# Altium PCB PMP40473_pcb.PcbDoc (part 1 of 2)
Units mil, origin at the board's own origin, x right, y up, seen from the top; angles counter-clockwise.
Board outline 3937.01 x 2598.43 mil, 2 copper layers (Top Layer, Bottom Layer), stack 62 mil thick; 79 components, 45 nets, 178 pads, 0 vias.
Unrouted connection lines stored in the file: 2.
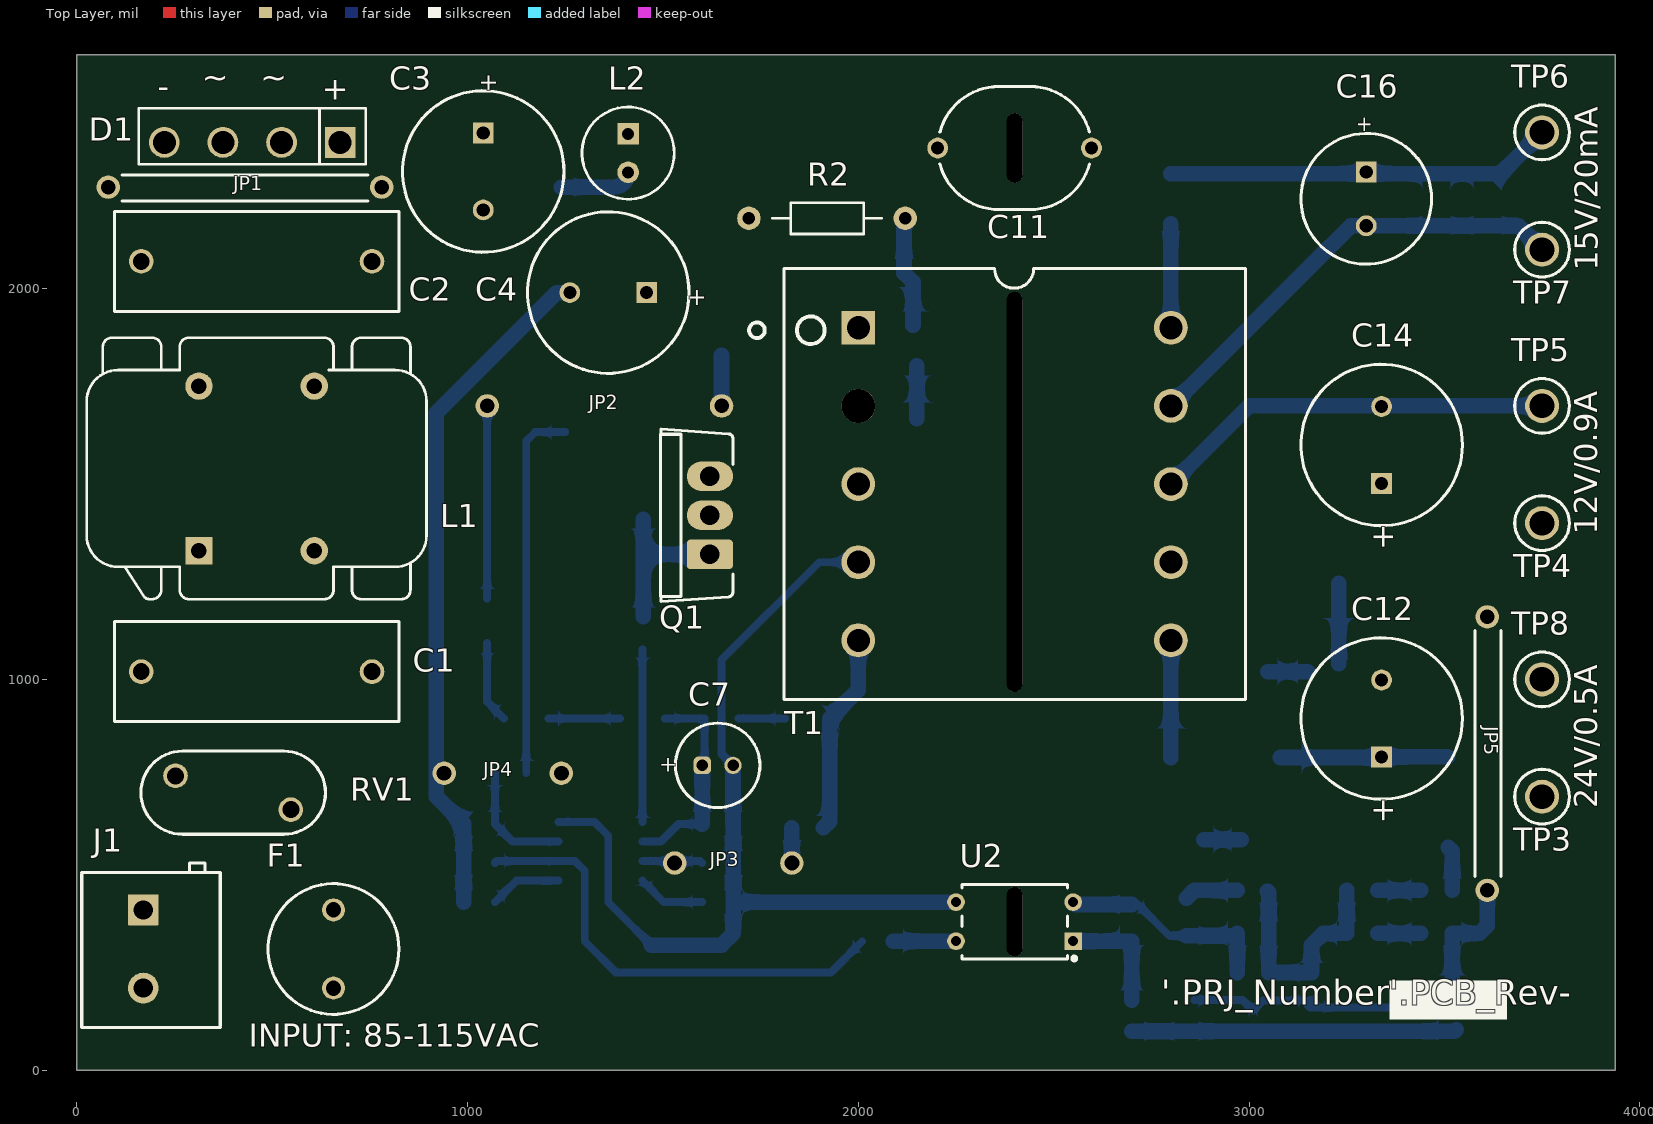
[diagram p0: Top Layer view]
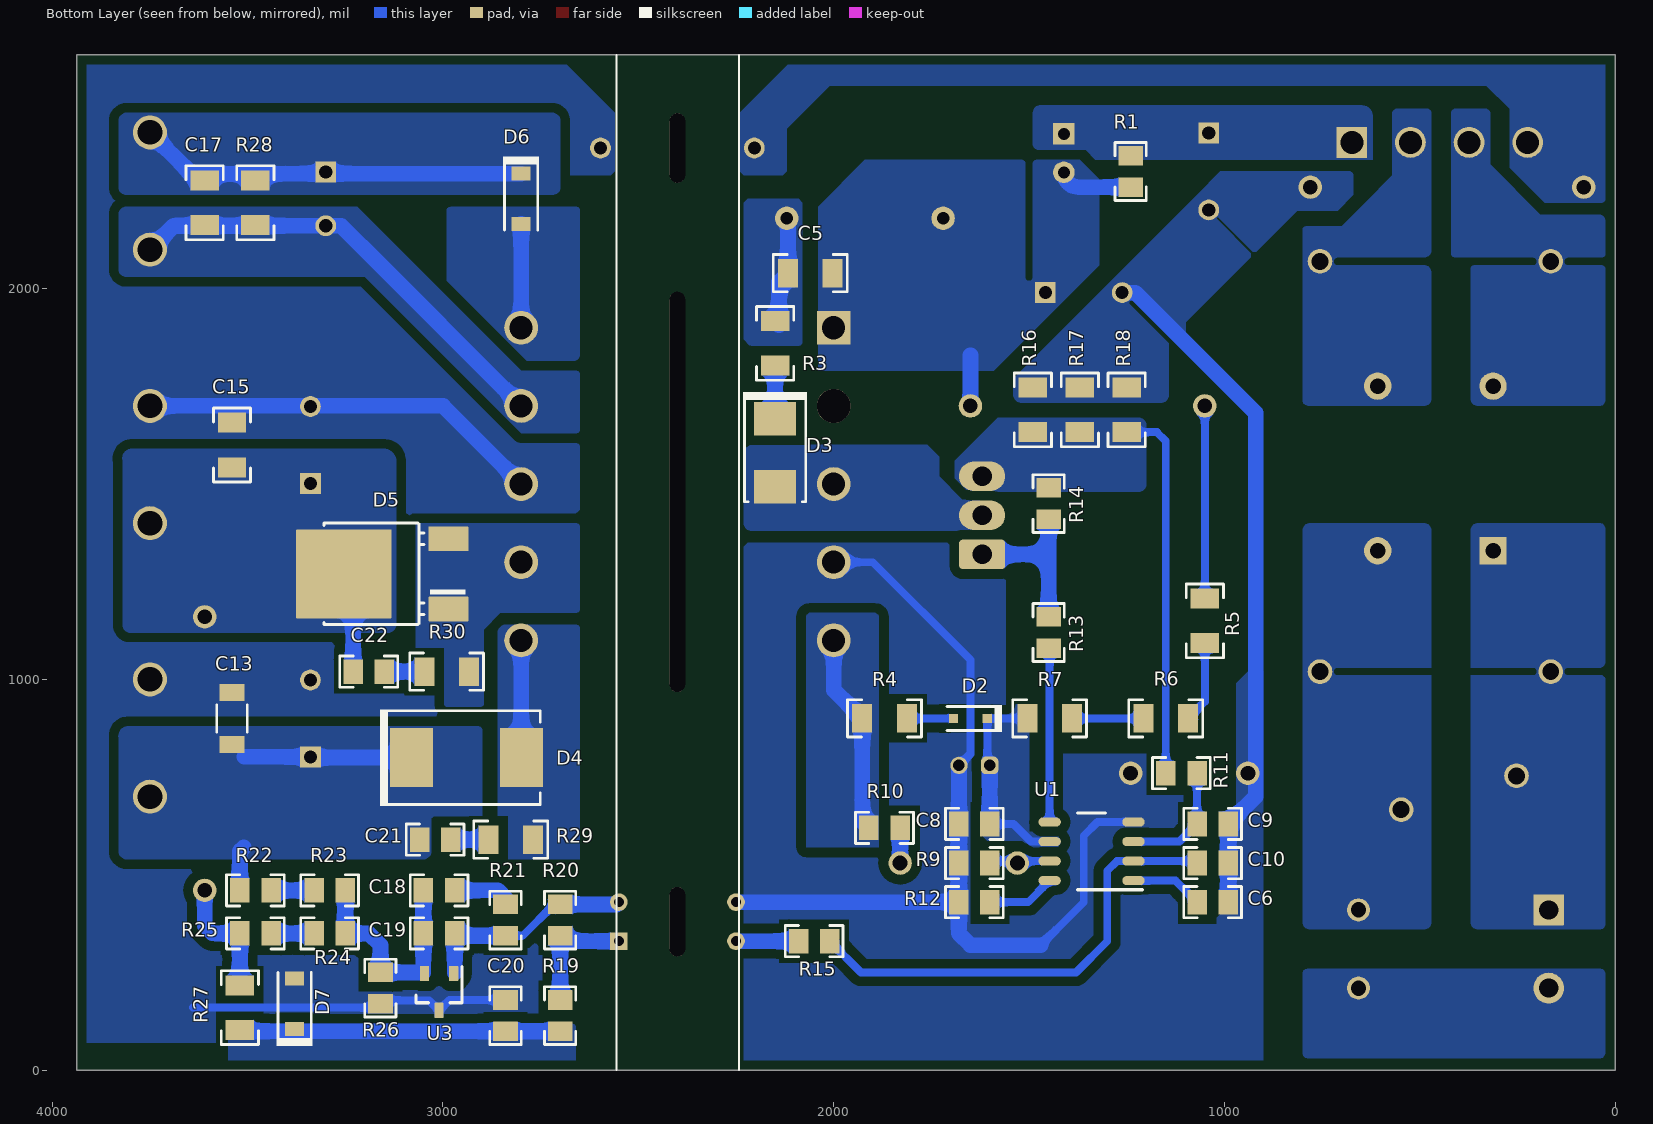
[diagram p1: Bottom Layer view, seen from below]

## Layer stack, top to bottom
Top Solder: solder mask 0.4, Solder Resist, Dk 3.5
Top Layer: signal copper 1.4
Dielectric1: core 59.2, FR-4, Dk 4.8
Bottom Layer: signal copper 1.4
Bottom Solder: solder mask 0.4, Solder Resist, Dk 3.5

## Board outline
0,0 3937.01,0 3937.01,2598.43 0,2598.43

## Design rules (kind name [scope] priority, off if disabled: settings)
AcuteAngle [All] p1: minimum=4.50000000000000E+0001 checktracksonly=FALSE
AssemblyTestPointUsage [All] p1: valid=2
BoardOutlineClearance BoardOutlineClearance_MountingHoles [OnCopper and InComponentClass('Mounting Holes')] p1: gap=40 ignorepadtopadclearanceinfootprint=FALSE
BoardOutlineClearance BoardOutlineClearance_Poly [OnCopper and IsPoly] p2: gap=25 ignorepadtopadclearanceinfootprint=FALSE
BoardOutlineClearance [OnCopper and Not InComponentClass('Logo') and not InComponentClass('FiducialMark') and not InRegion(1000,500,4000,800) and not InPoly] p3: gap=75 ignorepadtopadclearanceinfootprint=FALSE
Clearance Clearance_Keepouts [((IsTrack Or IsArc) And Not InPoly) And IsFree and IsKeepOut vs ((IsTrack Or IsArc) And Not InPoly) And IsFree and IsKeepOut] p1: gap=0 ignorepadtopadclearanceinfootprint=FALSE
Clearance Clearance_Poly [InPolygon] p2: gap=25 ignorepadtopadclearanceinfootprint=FALSE except(0: Arc-Hole Track-Hole SMDPad-Hole THPad-Hole Via-Hole Fill-Hole Poly-Hole Region-Hole Text-Hole)
Clearance Clearance_FiducialMark [IsKeepOut and InComponentClass('FiducialMark') vs IsPad and InComponentClass('FiducialMark')] p3: gap=0 ignorepadtopadclearanceinfootprint=FALSE
Clearance [All] p4: gap=7.87 ignorepadtopadclearanceinfootprint=FALSE except(0: Arc-Hole Track-Hole SMDPad-Hole THPad-Hole Via-Hole Fill-Hole Poly-Hole Region-Hole Text-Hole)
ComponentClearance ComponentClearance_MountingHoles_FiducialMarks [InComponentClass('Mounting Holes') vs InComponentClass('FiducialMark')] p1: gap=50 collisioncheckmode=3 verticalgap=10 showdistances=FALSE
ComponentClearance ComponentClearance_Shunt [InComponentClass('Header') vs InComponentClass('Shunt')] p2: gap=0 collisioncheckmode=3 verticalgap=0 showdistances=FALSE
ComponentClearance ComponentClearance_Logo [InComponentClass('Logo')] p3: gap=50 collisioncheckmode=3 verticalgap=10 showdistances=FALSE
ComponentClearance ComponentClearance_ScrewToNut [(HasFootprint('NY PMS 440 0025 PH')) vs (HasFootprint('Keystone_1902C'))] p4: gap=5 collisioncheckmode=3 verticalgap=10 showdistances=FALSE
ComponentClearance ComponentClearance_MountingHoles [InComponentClass('Mounting Holes')] p5: gap=250 collisioncheckmode=3 verticalgap=100000 showdistances=FALSE
ComponentClearance ComponentClearance_SmallPassives [HasFootprint('0201*') or HasFootprint('0402*') or HasFootprint('0508') or HasFootprint('0603*') or HasFootprint('0612') or HasFootprint('0805*') or HasFootprint('0815*') or HasFootprint('0830*') or HasFootprint('1206*') or HasFootprint('1210*') or HasFootprint('1808*') or HasFootprint('1812*') or HasFootprint('1825*') or HasFootprint('2010*') or HasFootprint('2220*') or HasFootprint('2225*') or HasFootprint('2512*') or HasFootprint('2728*') or HasFootprint('3518*') vs HasFootprint('0201*') or HasFootprint('0402*') or HasFootprint('0508') or HasFootprint('0603*') or HasFootprint('0612') or HasFootprint('0805*') or HasFootprint('0815*') or HasFootprint('0830*') or HasFootprint('1206*') or HasFootprint('1210*') or HasFootprint('1808*') or HasFootprint('1812*') or HasFootprint('1825*') or HasFootprint('2010*') or HasFootprint('2220*') or HasFootprint('2225*') or HasFootprint('2512*') or HasFootprint('2728*') or HasFootprint('3518*')] p6: gap=14.96 collisioncheckmode=3 verticalgap=10 showdistances=FALSE
ComponentClearance ComponentClearance_THtoSMT [IsThruComponent vs IsSMTComponent] p7: gap=40 collisioncheckmode=3 verticalgap=30 showdistances=FALSE
ComponentClearance ComponentClearance_THtoTH [IsThruComponent vs IsThruComponent] p8: gap=30 collisioncheckmode=3 verticalgap=30 showdistances=FALSE
ComponentClearance [All] p9: gap=30 collisioncheckmode=3 verticalgap=10 showdistances=FALSE
DiffPairsRouting [All] p1: maxlimit=100 minlimit=10 mostfreqgap=10 toplayer_minwidth=15 toplayer_maxwidth=15 toplayer_prefwidth=15 bottomlayer_minwidth=15 bottomlayer_maxwidth=15 bottomlayer_prefwidth=15 maxuncoupledlength=1000
FabricationTestPointUsage TestPointUsage [All] p1: valid=2 allowmultiple=FALSE
FabricationTestpoint Testpoint [All] p1: side=3 testpointundercomponent=TRUE minsize=40 maxsize=100 preferedsize=60 minholesize=0 maxholesize=40 preferedholesize=32 testpointgrid=1 allowsidetop=TRUE allowsidebottom=TRUE usegrid=TRUE gridtolerance=0.01
FanoutControl Fanout_LCC [IsLCC] p1: bgadir=Out bgaviamode=Centered fanoutstyle=Auto fanoutdirection=Alternating viagrid=1 // Fanout_LCC (Default Rule)
FanoutControl Fanout_BGA [IsBGA] p2: bgadir=Out bgaviamode=Centered fanoutstyle=Auto fanoutdirection=Alternating viagrid=1 // Fanout_BGA (Default Rule)
FanoutControl Fanout_Default [All] p4: bgadir=Out bgaviamode=Centered fanoutstyle=Auto fanoutdirection=Alternating viagrid=1 // Fanout_Default (Default Rule)
FanoutControl Fanout_Small [(CompPinCount < 5)] p5: bgadir=Out bgaviamode=Centered fanoutstyle=Auto fanoutdirection=OutThenIn viagrid=1 // Fanout_Small (Default Rule)
HoleSize [All] p1: absolutevalues=TRUE maxlimit=251 minlimit=7.87 maxpercent=80.000 minpercent=20.000
MinimumAnnularRing MinimumAnnularRing_ThermalPadVias [IsVia and InAnyComponent] p1: minimumring=5.91
MinimumAnnularRing [All] p2: minimumring=8
MinimumSolderMaskSliver MinimumSolderMaskSliver_Logo [InComponentClass('Logo') vs InComponentClass('Logo')] p1: minsoldermaskwidth=0.7
MinimumSolderMaskSliver [All] p2: minsoldermaskwidth=3.94
PlaneConnect [All] p1: planeconnectstyle=Relief reliefexpansion=10 reliefentries=4 reliefconductorwidth=10 reliefairgap=10
PolygonConnect [All] p1: connectstyle=Direct reliefconductorwidth=10 reliefentries=4 polygonreliefangle="90 Angle" airgapwidth=10
RoutingVias ThermalPadVias [IsVia and InAnyComponent] p1: holewidth=7.87 width=19.68 viastyle="Through Hole" minholewidth=7.87 minwidth=19.68 maxholewidth=12.99 maxwidth=23.62
RoutingVias [All] p2: holewidth=16 width=34 viastyle="Through Hole" minholewidth=7.87 minwidth=26 maxholewidth=40 maxwidth=65
SilkToBoardRegionClearance [Not ((IsComment or IsDesignator) And (Hide <> 'False')) and not InRegion(1000,500,4000,800)] p1:
SilkToSilkClearance SilkToSilkClearance_Pb-FreeLogo [(HasFootprint('Pb-Free_Overlay_Medium') OR HasFootprint('Pb-Free_Overlay_Small')) vs (HasFootprint('Pb-Free_Overlay_Medium') OR HasFootprint('Pb-Free_Overlay_Small'))] p1: silktosilkclearance=0
SilkToSilkClearance [All] p2: silktosilkclearance=4
SilkToSolderMaskClearance SilkToComponentPadClearance [(IsPad or IsFill or IsRegion) and InAnycomponent] p1: minsilkscreentomaskgap=5 clearancetoexposedcopper=TRUE
SilkToSolderMaskClearance "Silk to Solder Mask Opening" [All] p2: minsilkscreentomaskgap=4 clearancetoexposedcopper=FALSE
SolderMaskExpansion [All] p1: expansion=1.97
Width [All] p1: maxlimit=100 minlimit=20 preferedwidth=40 checkconnectedcopper=TRUE
15 further rules are at their usual default settings.

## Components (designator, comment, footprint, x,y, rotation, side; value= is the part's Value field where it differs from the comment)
C1 "890324025017" WCAP-FTX2_1800x600x1200 460,1020 r180 top value=0.1uF
C2 "890324025017" WCAP-FTX2_1800x600x1200 460,2070 r180 top value=0.1uF
C3 "EKXG201ELL330MJ20S" KL_1000x2000 1040,2300 r270 top value=33uF
C4 "EKXG201ELL330MJ20S" KL_1000x2000 1360,1990 r180 top value=33uF
C5 "GRM31BR72J222KW01L" 1206 2060,2040 r0 bottom value=2200pF
C6 "CC0805KRX7R9BB103" 0805_HV 1030,430 r0 bottom value=0.01uF
C7 "35YXH33MEFC5X11" Rubycon_500x1100 1640,780 r0 top value=33uF
C8 "C0805C104K5RACTU" 0805_HV 1640,630 r0 bottom value=0.1uF
C9 "GRM216R71E102KA01D" 0805_HV 1030,630 r180 bottom value=1000pF
C10 "GRM216R71E681KA01D" 0805_HV 1030,530 r180 bottom value=680pF
C11 "DE1E3KX222MA5BA01" CAPRD1000W60D1000H1400 2400,2360 r0 top value=2200pF
C12 "EKZE350ELL471MJ20S" Chemi-Con_1000x2000 3339.37,900 r90 top value=470uF
C13 "C3216X7R1H105K160AB" 1206_180 3540,900 r90 bottom value=1uF
C14 "EKMG250ELL102MJ20S" Chemi-Con_1000x2000 3339.37,1600 r90 top value=1000uF
C15 "C1206C105K3RACTU" 1206 3540,1600 r90 bottom value=1uF
C16 "EKMG250ELL221MHB5D" Chemi-Con_800x1150 3300,2230 r270 top value=220uF
C17 "C1206C105K3RACTU" 1206 3610,2220 r270 bottom value=1uF
C18 "C2012X7R1H224K125AA" 0805_HV 3010,460 r180 bottom value=0.22uF
C19 "08055C471KAT2A" 0805_HV 3010,350 r180 bottom value=470pF
C20 "GRM21BR71E104KA01L" 0805_HV 2840,139.5 r90 bottom value=0.1uF
C21 "GRM21BR71E104KA01L" 0805_HV 3020,590 r0 bottom value=0.1uF
C22 "GRM21BR71E104KA01L" 0805_HV 3190,1020 r0 bottom value=0.1uF
D1 "KBP06G" KBP 448.82,2374.33 r180 top value=600V
D2 "BAS20HT1G" SOD-323 1650,900 r0 bottom value=200V
D3 "RS1MB-13-F" SMB 2150,1580 r270 bottom value=1000V
D4 "B3100-13-F" SMC 2940,800 r180 bottom value=100V
D5 "MBRD360T4G" DPAK 3120,1270 r0 bottom value=60V
D6 "SBR0560S1-7" SOD-123 2800,2230 r270 bottom value=60V
D7 "MMSZ5242B-7-F" SOD-123 3380,170 r90 bottom value=12V
F1 "37205000001" FUSE_372 656.85,310 r90 top
J1 "ED120/2DS" On-Shore_ED120_2DS 170,310 r270 top
JP1 "923345-20-C" CONN_923345-07-C 430,2260 r0 top
JP2 "923345-20-C" CONN_923345-06-C 1350,1700 r0 top
JP3 "923345-20-C" 923345-03-C 1680,530 r0 top
JP4 "923345-20-C" 923345-03-C 1090,760 r180 top
JP5 "923345-20-C" CONN_923345-07-C 3610,810 r90 top
L1 "744823210" WE-CMB_M 460,1540 r90 top value=10mH
L2 "Inductor Iron" WE-TI_5075 1410.95,2347.09 r270 top value=220uH
Q1 "SPP06N80C3" TO-220AB 1620,1420 r90 top value=800V
R1 "Res2" 0805_HV 1240,2300 r270 bottom value=10.0k
R2 "CMF50150K00FHEB" CMF50 1920,2180 r180 top value=150k
R3 "CRCW120630R0JNEA" 1206 2150,1860 r90 bottom value=30
R4 "RC1206JR-070RL" 1206 1870,900 r0 bottom value=0
R5 "CRCW1206330KJNEA" 1206 1050,1150 r90 bottom value=330k
R6 "CRCW1206330KJNEA" 1206 1150,900 r180 bottom value=330k
R7 "CRCW1206330KJNEA" 1206 1447.28,900 r180 bottom value=330k
R9 "CRCW0805100KJNEA" 0805_HV 1640,530 r180 bottom value=100k
R10 "CRCW0805510KJNEA" 0805_HV 1870,620 r0 bottom value=510k
R11 "CRCW08051K50JNEA" 0805_HV 1110,760 r0 bottom value=1.5k
R12 "CRCW080510K0JNEA" 0805_HV 1640,430 r180 bottom value=10k
R13 "CRCW080510R0JNEA" 0805_HV 1450,1120 r270 bottom value=10
R14 "CRCW080547K0JNEA" 0805_HV 1450,1450 r270 bottom value=47k
R15 "CRCW08050000Z0EA" 0805_HV 2050,330 r180 bottom value=0
R16 "CRCW12061R50JNEA" 1206 1490,1690 r270 bottom value=1.5
R17 "CRCW12061R50JNEA" 1206 1370,1690 r270 bottom value=1.5
R18 "CRCW12061R50JNEA" 1206 1250,1690 r270 bottom value=1.5
R19 "CRCW08056K80JNEA" 0805_HV 2700,139.5 r90 bottom value=6.8k
R20 "CRCW08051K00JNEA" 0805_HV 2700,384 r90 bottom value=1.0k
R21 "CRCW080510K0JNEA" 0805_HV 2840,384 r270 bottom value=10k
R22 "CRCW08052K70JNEA" 0805_HV 3480,460 r0 bottom value=2.7k
R23 "CRCW080533K0JNEA" 0805_HV 3290,460 r0 bottom value=33k
R24 "CRCW080515K0FKEA" 0805_HV 3290,350 r0 bottom value=15.0k
R25 "CRCW08052K70JNEA" 0805_HV 3480,350 r0 bottom value=2.7k
R26 "CRCW08052K20JNEA" 0805_HV 3160,210 r90 bottom value=2.2k
R27 "CRCW120622R0JNEA" 1206 3520,160 r270 bottom value=22
R28 "CRCW120610K0JNEA" 1206 3480,2220 r90 bottom value=10k
R29 "CRCW120610K0JNEA" 1206 2826.64,590 r180 bottom value=10k
R30 "CRCW120610K0JNEA" 1206 2990.55,1020 r180 bottom value=10k
RV1 "S10K275E2" VAR_S10K275E2 400,710 r0 top value=275V
T1 "XFMR_RLTI-1072" EE25-13-7_2607 2400,1500 r0 top value=RLTI-1072
TP3 "5010" Keystone5010 3750,700 r90 top
TP4 "5010" Keystone5010 3750,1400 r90 top
TP5 "5011" Keystone5011 3750,1700 r90 top
TP6 "5010" Keystone5010 3750,2400 r90 top
TP7 "5011" Keystone5011 3750,2100 r90 top
TP8 "5011" Keystone5011 3750,1000 r90 top
U1 "UCC28600D" D0008A_N 1340,560 r0 bottom
U2 "FOD817A" DIP-4 2400,380 r180 top
U3 "TL431AIDBZT" DBZ0003A_N 3010,200 r270 bottom

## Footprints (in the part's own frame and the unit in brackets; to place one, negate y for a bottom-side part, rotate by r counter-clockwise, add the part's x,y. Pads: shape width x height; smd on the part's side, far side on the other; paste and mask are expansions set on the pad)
0805_HV [mil] "0805 with 30mil clearance between pads"
  rect 50x63 smd: 1(-40,0) 2(40,0)
  silkscreen extent -74,-40 74,40, body extent -43,-29 43,29, height 57
1206 [mm] "1206 from SM-752 data"
  rect 1.3x1.85 smd: 1(-1.45,0) 2(1.45,0)
  silkscreen extent -2.4,-1.21 2.4,1.21, body extent -1.7,-0.9 1.7,0.9, height 1.35
1206_180 [mm] "1206_180"
  rect 1.1x1.6 smd: 1(-1.7,0) 2(1.7,0)
  silkscreen extent -0.9,-1 0.9,1, body extent -1.75,-0.95 1.75,0.95, height 1.8
923345-03-C [mil] "Wire Jumper"
  round 60 hole 38: 1(-150,0) 2(150,0)
  body extent -163,-40 163,37, height 100
CAPRD1000W60D1000H1400 [mm] "Disk, Radial Capacitor"
  round 1.35 hole 0.85: 1(-5,0) 2(5,0)
  silkscreen extent -4.86,-4 4.86,4, body extent -5.67,-4 5.7,4, height 13.99
Chemi-Con_800x1150 [mm] "TH, 2-Leads, Dia 8mm"
  rect 1.35x1.35 hole 0.85: 1(-1.75,0)
  round 1.35 hole 0.85: 2(1.75,0)
  silkscreen extent -4.25,-4.25 4.25,4.25, body extent -4.22,-4.24 4.24,4.24, height 13.01
Chemi-Con_1000x2000 [mm] "TH, 2-Leads, Body 10x20mm, Pin Spacing 5mm"
  rect 1.35x1.35 hole 0.85: 1(-2.5,0)
  round 1.35 hole 0.85: 2(2.5,0)
  silkscreen extent -5.25,-5.25 5.25,5.25, body extent -5.25,-5.25 5.25,5.25, height 21.5
CMF50 [mil] "VIshay Metal Film Resistors 1/4W"
  round 60 hole 32: 1(-200,0) 2(200,0)
  silkscreen extent -140,-40 140,40, body extent -214,-40 214,40, height 80
CONN_923345-06-C [mil] "3M, Wire jumper, 600 mil lenght, Blue"
  round 60 hole 37: 1(-300,0) 2(300,0)
  body extent -313,-35 314,35, height 70
CONN_923345-07-C [mil] "3M, Wire jumper, 700 mil lenght, Violet"
  round 60 hole 37: 1(-350,0) 2(350,0)
  silkscreen extent -315,-35 315,31, body extent -363,-33 363,33, height 74
D0008A_N [mm] "SOIC, 8-Leads, Body 4.9x3.9mm, Pitch 1.27mm, IPC Medium Density"
  oval 1.45x0.6 smd: 1(-2.725,1.905) 2(-2.725,0.635) 3(-2.725,-0.635) 4(-2.725,-1.905) 5(2.725,-1.905) 6(2.725,-0.635) 7(2.725,0.635) 8(2.725,1.905)
  silkscreen extent -3.3,-2.5 0.9,2.5, body extent -3,-2.45 3,2.45, height 1.63
DBZ0003A_N [mm] "SOT23, 3-Leads, Body 2.9x1.3mm, Pitch 0.95mm, Lead Span 2.4mm, IPC Medium Density"
  rrect17% 1x0.6 smd: 1(-1.2,0.95) 2(-1.2,-0.95) 3(1.2,0)
  silkscreen extent -1.65,-1.5 0.7,1.5, body extent -1.26,-1.46 1.26,1.46, height 0.98
DIP-4 [mm] "DIP, 4-Leads, Body 6.86x4.83mm, Pitch 2.54mm"
  rect 1.15x1.15 hole 0.65: 1(-3.81,1.27)
  round 1.15 hole 0.65: 2(-3.81,-1.27) 3(3.81,-1.27) 4(3.81,1.27)
  silkscreen extent -4,-2.41 3.43,2.52, body extent -4.02,-2.41 4.02,2.41, height 5.59
DPAK [mm] "D-PAK, 3-Pads, Body 6.22x6.73mm (max), TO-252AA using nominal STEP model"
  rrect6% 2.6x1.6 smd: 1(-3.4,2.28) 3(-3.4,-2.28)
  rrect2% 6.2x5.8 smd paste-2.9: 4(3.4,0)
  silkscreen extent -4.5,-3.3 4.7,3.28, body extent -3.86,-3.29 5.84,3.29, height 2.48
EE25-13-7_2607 [mm] "THT, Body 29.21x27.94mm, 10Pins, Pitch 5.08mm"
  rect 2.2x2.2 hole 1.5: 1(-10.16,10.16)
  round 2.2 hole 2.2: 2(-10.16,5.08)
  round 2.2 hole 1.5: 3(-10.16,0) 4(-10.16,-5.08) 5(-10.16,-10.16) 6(10.16,-10.16) 7(10.16,-5.08) 8(10.16,0) 9(10.16,5.08) 10(10.16,10.16)
  silkscreen extent -17.26,-14 15,14, body extent -14,-13.75 14,13.75, height 19.91
FUSE_372 [mm] "LITTELFUSE"
  round 1.5 hole 1: 1(-2.54,0) 2(2.54,0)
  silkscreen extent -4.25,-4.25 4.25,4.25, body extent -4.25,-4.25 4.25,4.25, height 8
KBP [mm] "Diodes Inc Bridge Rectifier"
  rect 2x2 hole 1.5: 1(-5.715,0)
  round 2 hole 1.5: 2(-1.905,0) 3(1.905,0) 4(5.715,0)
  silkscreen extent -7.37,-2.23 7.38,1.42, body extent -7.37,-2.23 7.38,1.42, height 12.91
Keystone5010 [mil] "Keystone Multipurpose loops"
  round 87 hole 63: 1(0,0)
  silkscreen extent -70,-70 70,70, body extent -63,-63 63,62, height 319
Keystone5011 [mil] "Keystone Multipurpose loops"
  round 87 hole 63: 1(0,0)
  silkscreen extent -70,-70 70,70, body extent -63,-63 63,62, height 319
KL_1000x2000 [mm] "TH, 2-Leads, Dia 10mm, Pin Spacing 5mm"
  rect 1.35x1.35 hole 0.85: 1(-2.5,0)
  round 1.35 hole 0.85: 2(2.5,0)
  silkscreen extent -5.25,-5.25 5.25,5.25, body extent -5.25,-5.25 5.26,5.25, height 21.51
On-Shore_ED120_2DS [mm] "ONSHORE"
  rrect5% 2x2 hole 1.25: 1(-2.54,0)
  round 2 hole 1.25: 2(2.54,0)
  silkscreen extent -5.6,-4 5.12,5, body extent -5.78,-4 5.08,5, height 13
Rubycon_500x1100 [mm] "TH, 2-Leads, Dia 5mm,  Lead Spacing 2mm"
  rrect50% 1.125x1.125 hole 0.75: 1(-1,0)
  round 1.125 hole 0.75: 2(1,0)
  silkscreen extent -2.75,-2.75 2.75,2.75, body extent -2.73,-2.75 2.75,2.75, height 12.51
SMB [mil] "Molded Diode, 2-Leads, Body 5.4x3.6mm, IPC Medium Density, based on OnSemi component dimensions"
  rect 85x107.99 smd: 1(-87.01,0) 2(87.01,0)
  silkscreen extent -155,-82 125,82, body extent -106,-71 106,71, height 91
SMC [mil] "Molded Diode, 2-Leads, Body 6.9x5.8mm, IPC Medium Density, based on OnSemi component dimensions and land patterns"
  rect 110x150 smd: 1(-140.49,0) 2(140.49,0)
  silkscreen extent -221,-123 189,124, body extent -156,-116 156,116, height 91
SOD-123 [mm] "On Semi recommended land pattern"
  rect 0.915x1.22 smd: 1(-1.637,0) 2(1.637,0)
  silkscreen extent -2.74,-1.17 2.03,1.17, body extent -1.93,-0.9 1.93,0.9, height 1.35
SOD-323 [mm] "NXP recommended land pattern"
  rect 0.6x0.6 smd paste-0.05: 1(-1.1,0) 2(1.1,0)
  silkscreen extent -2.06,-0.86 1.53,0.86, body extent -1.3,-0.67 1.3,0.68, height 1.1
TO-220AB [mil] "Copied from Altium's version of TO3B"
  rrect25% 76x118.11 hole 50: 1(-100,0)
  oval 76x118.11 hole 50: 2(0,0) 3(100,0)
  silkscreen extent -221,-59 221,126, body extent -221,-59 221,126, height 765
VAR_S10K275E2 [mm] "EPCOS"
  round 1.6 hole 1.1: 1(-3.75,1.1) 2(3.75,-1.1)
  silkscreen extent -6,-2.7 6,2.7, body extent -5.98,-2.7 5.98,2.7, height 14.99
WCAP-FTX2_1800x600x1200 [mm] "TH, 2-Leads, Body 18x6mm, Lead Spacing 15mm"
  round 1.6 hole 1.1: 1(-7.5,0) 2(7.5,0)
  silkscreen extent -9.25,-3.25 9.25,3.25, body extent -9.25,-3.25 9.25,3.25, height 12.5
WE-CMB_M [mil] "Wurth"
  rect 70x70 hole 40: 1(-210.63,147.64)
  round 70 hole 40: 2(-210.63,-147.64) 3(210.63,-147.64) 4(210.63,147.64)
  silkscreen extent -335,-435 335,435, body extent -335,-394 335,394, height 1044
WE-TI_5075 [mm] "Wurth WE-TI 5075"
  rect 1.4x1.4 hole 0.787: 1(-1.25,0)
  round 1.4 hole 0.787: 2(1.25,0)
  silkscreen extent -3,-3 3,3, body extent -3,-3 3,3, height 8.5

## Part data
C1 C2: "CAP, Film, 0.1 µF, X2 275 VAC, +/- 10%, TH", Cap_Case=18x6x12mm, Manufacturer="Wurth Elektronik", Supplier Part Number 1=732-5898-ND, Tolerance_%=10, ValueDisplayed=0.1µF
C3 C4: library part EKXG401EC3330ML20S, "CAP, AL, 33 µF, 400 V, +/- 20%, TH", Cap_Case=10x20mm, Manufacturer=Chemi-Con, Tolerance_%=20, Value2=200V, ValueDisplayed=33µF
C5: "CAP, CERM, 2200 pF, 630 V,+/- 10%, X7R, 1206", Cap_Case=1206, Manufacturer=MuRata, Supplier Part Number 1=490-3508-1-ND, TempCo=X7R, Tolerance_%=10, Value2=630V, ValueDisplayed=2200pF
C6: "CAP, CERM, 0.01 µF, 50 V,+/- 10%, X7R, 0805", Cap_Case=0805, Manufacturer="Yageo America", Supplier Part Number 1=311-1136-1-ND, TempCo=X7R, Tolerance_%=10, Value2=50V, ValueDisplayed=0.01µF
C7: "CAP, AL, 33 µF, 35 V, +/- 20%, TH", Cap_Case=5x11mm, Manufacturer=Rubycon, Supplier Part Number 1=35YXH33MEFC5X11-ND, Tolerance_%=20, Value2=35V, ValueDisplayed=33µF
C8: "CAP, CERM, 0.1 µF, 50 V,+/- 10%, X7R, 0805", Cap_Case=0805, Manufacturer=Kemet, Supplier Part Number 1=399-1170-1-ND, TempCo=X7R, Tolerance_%=10, Value1="0.064 ohm", Value2=50V, ValueDisplayed=0.1µF
C9: "CAP, CERM, 1000 pF, 25 V,+/- 10%, X7R, 0805", Cap_Case=0805, Manufacturer=MuRata, Supplier Part Number 1=GRM216R71E102KA01D-ND, TempCo=X7R, Tolerance_%=10, Value2=25V, ValueDisplayed=1000pF
C10: "CAP, CERM, 680 pF, 25 V,+/- 10%, X7R, 0805", Cap_Case=0805, Manufacturer=MuRata, Supplier Part Number 1=GRM216R71E681KA01D-ND, TempCo=X7R, Tolerance_%=10, Value2=25V, ValueDisplayed=680pF
C11: "CAP, CERM, 2200 pF, 250 V, +/- 20%, E, Disc 10x8mm", Cap_Case=CAPRD1000W60D1000H1400, Manufacturer=MuRata, Supplier Part Number 1=490-7048-ND, TempCo=E, Tolerance_%=20, Value1=Unknown, Value2=250V, ValueDisplayed=2200pF
C12: "CAP, AL, 470 µF, 35 V, +/- 20%, TH", Cap_Case=10x20, Manufacturer=Chemi-Con, Supplier Part Number 1=565-1694-ND, Tolerance_%=20, Value2=35V, ValueDisplayed=470µF
C13: "CAP, CERM, 1 µF, 50 V,+/- 10%, X7R, 1206", Cap_Case=1206, Manufacturer=TDK, Supplier Part Number 1=445-1423-1-ND, TempCo=X7R, Tolerance_%=10, Value1="0.009289 ohm", Value2=50V, ValueDisplayed=1µF
C14: "CAP, AL, 1000 µF, 25 V, +/- 20%, TH", Cap_Case=10x20mm, Manufacturer=Chemi-Con, Supplier Part Number 1=565-1311-ND, Tolerance_%=20, Value2=25V, ValueDisplayed=1000µF
C15 C17: "CAP, CERM, 1 µF, 25 V,+/- 10%, X7R, 1206", Cap_Case=1206, Manufacturer=Kemet, Supplier Part Number 1=399-1255-1-ND, TempCo=X7R, Tolerance_%=10, Value1="0.011 ohm", Value2=25V, ValueDisplayed=1µF
C16: "CAP, AL, 220 µF, 25 V, +/- 20%, TH", Cap_Case=8x11.5mm, Manufacturer=Chemi-Con, Supplier Part Number 1=565-1308-ND, Tolerance_%=20, Value2=25V, ValueDisplayed=220µF
C18: "CAP, CERM, 0.22 µF, 50 V,+/- 10%, X7R, 0805", Cap_Case=0805, Manufacturer=TDK, Supplier Part Number 1=445-1350-1-ND, TempCo=X7R, Tolerance_%=10, Value1="0.016949 ohm", Value2=50V, ValueDisplayed=0.22µF
C19: "CAP, CERM, 470 pF, 50 V,+/- 10%, X7R, 0805", Cap_Case=0805, Manufacturer=AVX, Supplier Part Number 1=478-1367-1-ND, TempCo=X7R, Tolerance_%=10, Value1="0.454 ohm", Value2=50V, ValueDisplayed=470pF
C20 C21 C22: "CAP, CERM, 0.1 µF, 25 V,+/- 10%, X7R, 0805", Cap_Case=0805, Manufacturer=MuRata, Supplier Part Number 1=490-1673-1-ND, TempCo=X7R, Tolerance_%=10, Value2=25V, ValueDisplayed=0.1µF
D1: "Diode, Switching-Bridge, 600 V, 1.5 A, TH", Manufacturer="Diodes Inc.", Supplier Part Number 1=KBP06G-ND, Value1=1.5A, Value2=1.1V
D2: "Diode, Switching, 200 V, 0.2 A, AEC-Q101, SOD-323", Manufacturer="ON Semiconductor", Supplier Part Number 1=BAS20HT1GOSCT-ND, Value1=0.2A, Value2=1.25V
D3: "Diode, P-N, 1000 V, 1 A, SMB", Manufacturer="Diodes Inc.", Supplier Part Number 1=RS1MB-FDICT-ND, Value1=1A, Value2=1.3V
D4: "Diode, Schottky, 100 V, 3 A, SMC", Manufacturer="Diodes Inc.", Supplier Part Number 1=B3100-FDICT-ND, Value1=3A, Value2=0.79V
D5: "Diode, Schottky, 60 V, 3 A, DPAK", Manufacturer="ON Semiconductor", Supplier Part Number 1=MBRD360T4GOSCT-ND, Value1=3A, Value2=0.6V
D6: "Diode, Schottky, 60 V, 0.5 A, SOD-123", Manufacturer="Diodes Inc.", Supplier Part Number 1=SBR0560S1DICT-ND, Value1=0.5A, Value2=0.5V
D7: "Diode, Zener, 12 V, 500 mW, SOD-123", Manufacturer="Diodes Inc.", Power_W=0.5, Supplier Part Number 1=MMSZ5242B-FDICT-ND, Value1=0.5W
F1: "Fuse, 0.5 A, 250VAC/VDC, TH", Irating_A=0.5, Manufacturer=Littelfuse, Supplier Part Number 1=WK4241CT-ND
J1: library part CMP-0074910-1, "Terminal Block, 5.08 mm, 2x1, Brass, TH", Color=Blue, Current_A=15A, Manufacturer="On-Shore Technology", Supplier Part Number 1=ED1609-ND, Voltage_V=300V
JP1 JP5: library part CMP-0074936-1, "Jumper Wire, 700mil spacing, Violet, pkg of 150, TH", Manufacturer=3M, PartNumber=923345-07-C, Supplier Part Number 1=923345-07-ND
JP2: library part CMP-0074937-1, "Jumper Wire, 600mil spacing, Blue, pkg of 150, TH", Manufacturer=3M, PartNumber=923345-06-C, Supplier Part Number 1=923345-06-ND
JP3 JP4: library part CMP-0055440-1, "Jumper Wire, 300mil spacing, Orange, pkg of 200", Manufacturer=3M, PartNumber=923345-03-C, Supplier Part Number 1=923345-03-ND
L1: "Coupled inductor, 10 mH, 2 A, 0.125 ohm, TH", Manufacturer="Wurth Elektronik", Supplier Part Number 1=732-1447-ND, ValueDisplayed=10mH
L2: library part 7447462221, "Inductor, Unshielded Drum Core, Ferrite, 220 µH, 0.5 A, 0.96 ohm, TH", Manufacturer="Wurth Elektronik", Supplier Part Number 1=732-2574-ND, Value1="0.96 ohm", Value2=0.5A, ValueDisplayed=220µH
Q1: "MOSFET, N-CH, 800 V, 6 A, TO-220AB", Alternate Manufacturer=None, Manufacturer="Infineon Technologies", Supplier Part Number 1=SPP06N80C3IN-ND, Value1="0.9 ohm", Value2="41 nC"
R1: library part CRCW080510K0FKEA, "RES, 10.0 k, 1%, 0.125 W, 0805", Manufacturer=Vishay-Dale, Power_W=0.125, Supplier Part Number 1=541-10.0KCCT-ND, TempCo="100 ppm/C", Tolerance_%=1, Value1=1%, Value2=0.125W, Value_Code=10k0, ValueDisplayed=10.0k
R2: "RES, 150 k, 1%, 0.25 W, Axial", Manufacturer=Vishay-Dale, Power_W=0.25, Supplier Part Number 1=CMF150KQFCT-ND, TempCo="50 ppm/C", Tolerance_%=1, Value1=1%, Value2=0.25W, Value_Code=150k
R3: "RES, 30, 5%, 0.25 W, 1206", Manufacturer=Vishay-Dale, Power_W=0.25, Supplier Part Number 1=541-30ECT-ND, TempCo="200 ppm/C", Tolerance_%=5, Value1=5%, Value2=0.25W, Value_Code=30R0, ValueDisplayed=30
R4: "RES, 0, 5%, 0.25 W, 1206", Manufacturer="Yageo America", Power_W=0.25, Supplier Part Number 1=311-0.0ERCT-ND, TempCo="200 ppm/C", Tolerance_%=5, Value1=5%, Value2=0.25W, Value_Code=0000, ValueDisplayed=0
R5 R6 R7: "RES, 330 k, 5%, 0.25 W, 1206", Manufacturer=Vishay-Dale, Power_W=0.25, Supplier Part Number 1=541-330KECT-ND, TempCo="200 ppm/C", Tolerance_%=5, Value1=5%, Value2=0.25W, Value_Code=330k
R9: "RES, 100 k, 5%, 0.125 W, 0805", Manufacturer=Vishay-Dale, Power_W=0.125, Supplier Part Number 1=541-100KACT-ND, TempCo="200 ppm/C", Tolerance_%=5, Value1=5%, Value2=0.125W, Value_Code=100k
R10: "RES, 510 k, 5%, 0.125 W, 0805", Manufacturer=Vishay-Dale, Power_W=0.125, Supplier Part Number 1=541-510KACT-ND, TempCo="200 ppm/C", Tolerance_%=5, Value1=5%, Value2=0.125W, Value_Code=510k
R11: "RES, 1.5 k, 5%, 0.125 W, 0805", Manufacturer=Vishay-Dale, Power_W=0.125, Supplier Part Number 1=541-1.5KACT-ND, TempCo="200 ppm/C", Tolerance_%=5, Value1=5%, Value2=0.125W, Value_Code=1k50, ValueDisplayed=1.5k
R12 R21: "RES, 10 k, 5%, 0.125 W, 0805", Manufacturer=Vishay-Dale, Power_W=0.125, Supplier Part Number 1=541-10KACT-ND, TempCo="200 ppm/C", Tolerance_%=5, Value1=5%, Value2=0.125W, Value_Code=10k0, ValueDisplayed=10k
R13: "RES, 10, 5%, 0.125 W, 0805", Manufacturer=Vishay-Dale, Power_W=0.125, Supplier Part Number 1=541-10ACT-ND, TempCo="200 ppm/C", Tolerance_%=5, Value1=5%, Value2=0.125W, Value_Code=10R0, ValueDisplayed=10
R14: "RES, 47 k, 5%, 0.125 W, 0805", Manufacturer=Vishay-Dale, Power_W=0.125, Supplier Part Number 1=541-47KACT-ND, TempCo="200 ppm/C", Tolerance_%=5, Value1=5%, Value2=0.125W, Value_Code=47k0, ValueDisplayed=47k
R15: "RES, 0, 5%, 0.125 W, 0805", Manufacturer=Vishay-Dale, Power_W=0.125, Supplier Part Number 1=541-0.0ACT-ND, TempCo="200 ppm/C", Tolerance_%=5, Value1=5%, Value2=0.125W, Value_Code=0000, ValueDisplayed=0
R16 R17 R18: "RES, 1.5, 5%, 0.25 W, 1206", Manufacturer=Vishay-Dale, Power_W=0.25, Supplier Part Number 1=541-1.5ECT-ND, TempCo="200 ppm/C", Tolerance_%=5, Value1=5%, Value2=0.25W, Value_Code=1R50, ValueDisplayed=1.5
R19: "RES, 6.8 k, 5%, 0.125 W, 0805", Manufacturer=Vishay-Dale, Power_W=0.125, Supplier Part Number 1=541-6.8KACT-ND, TempCo="200 ppm/C", Tolerance_%=5, Value1=5%, Value2=0.125W, Value_Code=6k80, ValueDisplayed=6.8k
R20: "RES, 1.0 k, 5%, 0.125 W, 0805", Manufacturer=Vishay-Dale, Power_W=0.125, Supplier Part Number 1=541-1.0KACT-ND, TempCo="200 ppm/C", Tolerance_%=5, Value1=5%, Value2=0.125W, Value_Code=1k00, ValueDisplayed=1.0k
R22 R25: "RES, 2.7 k, 5%, 0.125 W, 0805", Manufacturer=Vishay-Dale, Power_W=0.125, Supplier Part Number 1=541-2.7KACT-ND, TempCo="200 ppm/C", Tolerance_%=5, Value1=5%, Value2=0.125W, Value_Code=2k70, ValueDisplayed=2.7k
R23: "RES, 33 k, 5%, 0.125 W, 0805", Manufacturer=Vishay-Dale, Power_W=0.125, Supplier Part Number 1=541-33KACT-ND, TempCo="200 ppm/C", Tolerance_%=5, Value1=5%, Value2=0.125W, Value_Code=33k0, ValueDisplayed=33k
R24: "RES, 15.0 k, 1%, 0.125 W, 0805", Manufacturer=Vishay-Dale, Power_W=0.125, Supplier Part Number 1=541-15.0KCCT-ND, TempCo="100 ppm/C", Tolerance_%=1, Value1=1%, Value2=0.125W, Value_Code=15k0, ValueDisplayed=15.0k
R26: "RES, 2.2 k, 5%, 0.125 W, 0805", Manufacturer=Vishay-Dale, Power_W=0.125, Supplier Part Number 1=541-2.2KACT-ND, TempCo="200 ppm/C", Tolerance_%=5, Value1=5%, Value2=0.125W, Value_Code=2k20, ValueDisplayed=2.2k
R27: "RES, 22, 5%, 0.25 W, 1206", Manufacturer=Vishay-Dale, Power_W=0.25, Supplier Part Number 1=541-22ECT-ND, TempCo="200 ppm/C", Tolerance_%=5, Value1=5%, Value2=0.25W, Value_Code=22R0, ValueDisplayed=22
R28 R29 R30: "RES, 10 k, 5%, 0.25 W, 1206", Manufacturer=Vishay-Dale, Power_W=0.25, Supplier Part Number 1=541-10KECT-ND, TempCo="200 ppm/C", Tolerance_%=5, Value1=5%, Value2=0.25W, Value_Code=10k0, ValueDisplayed=10k
RV1: "Varistor 275V RMS 10MM Radial, TH", Manufacturer=TDK, Supplier Part Number 1=495-1433-ND
T1: library part EF25, "Transformer, Flyback", MFR=Renco, Part Number=RLTI-1072
TP3 TP4 TP6: "Test Point, Multipurpose, Red, TH", Color=Red, Manufacturer=Keystone, Supplier Part Number 1=36-5010-ND
TP5 TP7 TP8: "Test Point, Multipurpose, Black, TH", Color=Black, Manufacturer=Keystone, Supplier Part Number 1=36-5011-ND
U1: "Quasi-Resonant Flyback Green-Mode Controller with Current Control, 99 % Duty Cycle, -40 to +105 degC, 8-pin SOIC (D), Green (RoHS & no Sb/Br)", Alternate Manufacturer="Texas Instruments", Alternate PartNumber=Equivalent, Frequency(Max)(kHz)=130, Rating=Catalog, Supplier Part Number 1=296-19799-5-ND
U2: "Optocoupler, 5 kV, 80-160% CTR, TH", Manufacturer="Fairchild Semiconductor", Supplier Part Number 1=FOD817A-ND, Voltage_Isolation_Vrms=5000V
U3: "Adjustable Precision Shunt Regulator, 34 ppm / degC, 100 mA, -40 to 85 degC, 3-pin SOT-23 (DBZ), Green (RoHS & no Sb/Br)", Alternate Manufacturer="Texas Instruments", Alternate PartNumber=Equivalent, Rating=Catalog, Supplier Part Number 1=296-26711-2-ND, Temp Coeff(Max)(ppm/ degree C)=92, Temp Coeff(Typ)(ppm/ degree C)=34

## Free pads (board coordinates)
  oval 39.37x177.17 hole 39.37 slot 177.17 at 90 deg: 1(2400,380) 3(2400,2360)
  oval 39.37x1023.62 hole 39.37 slot 1023.62 at 90 deg: 2(2400,1480)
